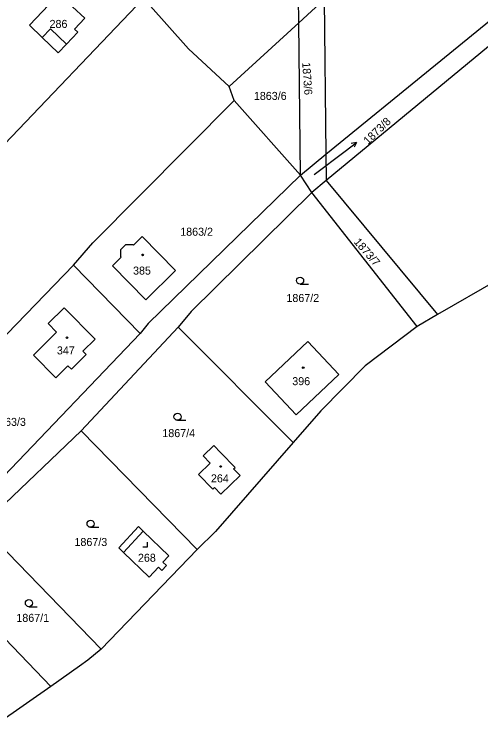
# Model space of a CAD drawing. Extents: x -725728 to -720881, y -1068679 to -1063504.
# Drawn here: x -722733.9 to -722634.8, y -1067669.1 to -1067518.7 of the extents above; entities that cross this region are included whole.
import ezdxf

# ---------------------------------------------------------------- set-up
doc = ezdxf.new("R2010")
doc.units = 0
for name, color, linetype in [('Hranice parcel', 7, 'Continuous'), ('Parcelní čísla', 7, 'Continuous'), ('Pop  PČ popisy', 7, 'Continuous'), ('Vnitřní kresba', 7, 'Continuous'), ('Značky budov', 7, 'Continuous'), ('Značky kultur', 7, 'Continuous')]:
    doc.layers.add(name, color=color, linetype=linetype)

msp = doc.modelspace()

# ---------------------------------------------------------------- linework, layer by layer
at = {"layer": 'Hranice parcel'}
for p, q in [((-722673.5, -1067520.47), (-722673.85, -1067489.62)), ((-722739.61, -1067549.94), (-722706.43, -1067515.29)), ((-722673.5, -1067520.47), (-722668.09, -1067515.49)), ((-722668.09, -1067515.49), (-722667.71, -1067548.37)), ((-722688.25, -1067534.02), (-722673.5, -1067520.47)), ((-722673.13, -1067552.86), (-722673.5, -1067520.47)), ((-722687.2, -1067536.98), (-722688.25, -1067534.02)), ((-722687.2, -1067536.98), (-722673.13, -1067552.86)), ((-722673.13, -1067552.86), (-722667.71, -1067548.37)), ((-722667.71, -1067548.37), (-722667.64, -1067553.99)), ((-722670.72, -1067556.54), (-722673.13, -1067552.86)), ((-722667.64, -1067553.99), (-722670.72, -1067556.54)), ((-722667.64, -1067553.99), (-722644.01, -1067582.46)), ((-722648.38, -1067585), (-722670.72, -1067556.54)), ((-722623.15, -1067570.34), (-722644.01, -1067582.46)), ((-722750.47, -1067602.06), (-722721.36, -1067571.93)), ((-722721.36, -1067571.93), (-722707.15, -1067586.48)), ((-722644.01, -1067582.46), (-722648.38, -1067585)), ((-722699.09, -1067585.09), (-722719.73, -1067607.17)), ((-722699.09, -1067585.09), (-722674.71, -1067609.61)), ((-722707.15, -1067586.48), (-722736.14, -1067616.76)), ((-722719.73, -1067607.17), (-722740.82, -1067627.32)), ((-722695.09, -1067632.31), (-722719.73, -1067607.17)), ((-722674.71, -1067609.61), (-722691.16, -1067628.54)), ((-722715.42, -1067653.53), (-722740.82, -1067627.32)), ((-722691.16, -1067628.54), (-722695.09, -1067632.31)), ((-722695.09, -1067632.31), (-722715.42, -1067653.53)), ((-722750.4, -1067636.25), (-722726.13, -1067661.43)), ((-722720.06, -1067657.12), (-722726.13, -1067661.43)), ((-722726.13, -1067661.43), (-722737.27, -1067669.14))]:
    msp.add_line(p, q, dxfattribs=at)
for points in [[(-722667.71, -1067548.37), (-722621.17, -1067510.37), (-722585.92, -1067488.55)], [(-722583.62, -1067492), (-722618.19, -1067513.05), (-722667.64, -1067553.99)], [(-722721.1, -1067521.82), (-722720.4, -1067522.47), (-722722.78, -1067525.03), (-722724.55, -1067526.88), (-722727.98, -1067523.58), (-722730.64, -1067521.03), (-722726.54, -1067516.71), (-722726.3, -1067516.93), (-722724.18, -1067514.65), (-722718.95, -1067519.5), (-722721.1, -1067521.82)], [(-722705.53, -1067516.3), (-722696.89, -1067526.05), (-722688.25, -1067534.02)], [(-722721.36, -1067571.93), (-722717.21, -1067567.25), (-722687.2, -1067536.98)], [(-722673.13, -1067552.86), (-722705.44, -1067584.34), (-722707.15, -1067586.48)], [(-722670.72, -1067556.54), (-722696.37, -1067581.78), (-722699.09, -1067585.09)], [(-722699.64, -1067573.09), (-722705.96, -1067579.3), (-722713.02, -1067572.13), (-722711.19, -1067570.27), (-722711.3, -1067570.16), (-722711.29, -1067568.65), (-722710.22, -1067567.59), (-722708.68, -1067567.58), (-722708.57, -1067567.69), (-722706.72, -1067565.87), (-722699.64, -1067573.09)], [(-722725.05, -1067595.85), (-722729.81, -1067591.06), (-722724.91, -1067586.2), (-722726.69, -1067584.35), (-722723.34, -1067581), (-722716.74, -1067587.67), (-722719.31, -1067590.25), (-722718.63, -1067590.96), (-722721.75, -1067594.03), (-722722.51, -1067593.32), (-722725.05, -1067595.85)], [(-722648.38, -1067585), (-722659.36, -1067593.34), (-722668.82, -1067602.87), (-722674.71, -1067609.61)], [(-722674.04, -1067603.74), (-722680.65, -1067596.72), (-722671.56, -1067588.18), (-722664.95, -1067595.14), (-722674.04, -1067603.74)], [(-722690.02, -1067620.61), (-722685.94, -1067616.65), (-722687.35, -1067615.2), (-722687.03, -1067614.89), (-722690.03, -1067611.79), (-722691.54, -1067610.24), (-722693.81, -1067612.45), (-722692.31, -1067614.01), (-722694.79, -1067616.43), (-722691.72, -1067619.49), (-722691.4, -1067619.18), (-722690.02, -1067620.61)], [(-722711.7, -1067632), (-722707.53, -1067627.47), (-722706.55, -1067628.41), (-722701.06, -1067633.67), (-722702.34, -1067635.05), (-722701.6, -1067635.74), (-722702.55, -1067636.76), (-722703.29, -1067636.07), (-722705.25, -1067638.18), (-722710.7, -1067632.96), (-722711.7, -1067632)], [(-722715.42, -1067653.53), (-722718.28, -1067655.85), (-722720.06, -1067657.12)]]:
    msp.add_lwpolyline(points, dxfattribs=at)
at = {"layer": 'Pop  PČ popisy'}
for p, q in [((-722663.65, -1067547.72), (-722661.25, -1067545.91)), ((-722661.25, -1067545.91), (-722662.35, -1067546.12)), ((-722661.25, -1067545.91), (-722661.75, -1067546.92)), ((-722670.2, -1067552.73), (-722663.65, -1067547.72))]:
    msp.add_line(p, q, dxfattribs=at)
at = {"layer": 'Vnitřní kresba'}
for p, q in [((-722726.21, -1067521.74), (-722727.98, -1067523.58)), ((-722722.78, -1067525.03), (-722726.21, -1067521.74)), ((-722710.7, -1067632.96), (-722706.55, -1067628.41))]:
    msp.add_line(p, q, dxfattribs=at)
at = {"layer": 'Značky budov'}
for centre in [(-722706.65, -1067569.77), (-722722.71, -1067587.36), (-722672.55, -1067593.72), (-722690.08, -1067614.71)]:
    msp.add_circle(centre, 0.175, dxfattribs=at)
at = {"layer": 'Značky kultur'}
for p, q in [((-722673.2, -1067575.99), (-722671.45, -1067575.99)), ((-722699.24, -1067604.9), (-722697.49, -1067604.9)), ((-722717.71, -1067627.62), (-722715.96, -1067627.62)), ((-722705.59, -1067631.79), (-722705.59, -1067630.79)), ((-722706.59, -1067631.79), (-722705.59, -1067631.79)), ((-722730.8, -1067644.48), (-722729.05, -1067644.48))]:
    msp.add_line(p, q, dxfattribs=at)
for centre in [(-722673.2, -1067575.24), (-722699.24, -1067604.15), (-722717.71, -1067626.87), (-722730.8, -1067643.73)]:
    msp.add_circle(centre, 0.75, dxfattribs=at)

# ---------------------------------------------------------------- texts
at = {"layer": 'Parcelní čísla'}
for s, p in [('286', (-722726.41, -1067521.58)), ('1863/6', (-722683.02, -1067536.87)), ('1863/2', (-722698.66, -1067565.71)), ('385', (-722708.68, -1067573.96)), ('1867/2', (-722676.11, -1067579.78)), ('347', (-722724.85, -1067590.91)), ('396', (-722674.87, -1067597.44)), ('1863/3', (-722738.39, -1067606.09)), ('1867/4', (-722702.46, -1067608.47)), ('264', (-722692.14, -1067618.08)), ('1867/3', (-722721.12, -1067631.59)), ('268', (-722707.64, -1067634.94)), ('1867/1', (-722733.46, -1067647.7))]:
    msp.add_text(s, height=1.7, dxfattribs=at).set_placement(p)
for s, rotation, p in [('1873/6', 274, (-722672.76, -1067528.94)), ('1873/8', 44, (-722658.77, -1067546.46)), ('1873/7', 311, (-722661.9, -1067567.1))]:
    msp.add_text(s, height=1.7, rotation=rotation, dxfattribs=at).set_placement(p)

doc.saveas('drawing.dxf')
